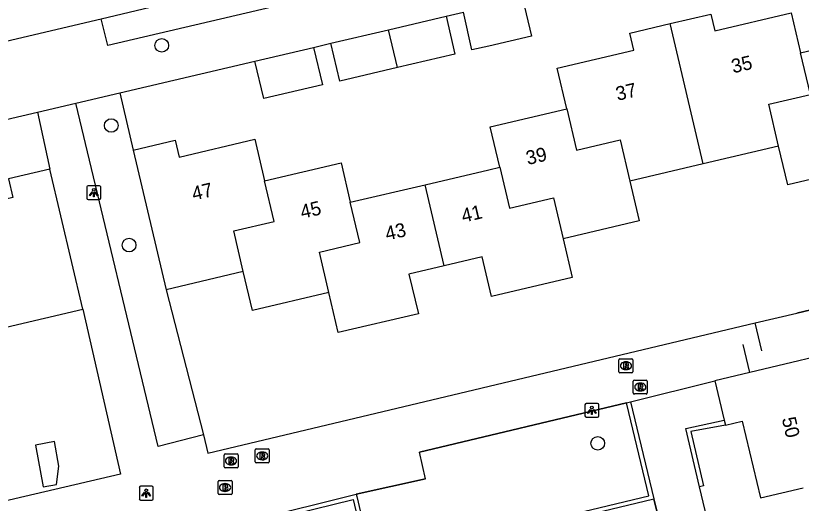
# Model space of a CAD drawing. Extents: x 158038 to 159242, y 380133 to 381214.
# Drawn here: x 158966.1 to 159022.4, y 380563.6 to 380598.6 of the extents above; entities that cross this region are included whole.
import ezdxf

# ---------------------------------------------------------------- set-up
doc = ezdxf.new("R2010")
doc.units = 0
for name, color, linetype in [('IMGEO_Boom', 7, 'Continuous'), ('IMGEO_Brandkraan', 7, 'Continuous'), ('IMGEO_Groenvoorziening', 7, 'Continuous'), ('IMGEO_Hek', 7, 'Continuous'), ('IMGEO_Lichtpunt', 7, 'Continuous'), ('IMGEO_Muur', 7, 'Continuous'), ('IMGEO_Pand', 7, 'Continuous'), ('IMGEO_Pand_nummerreeks', 7, 'Continuous'), ('IMGEO_Rijbaan_lokaal_gesloten', 7, 'Continuous'), ('IMGEO_Rioolput', 7, 'Continuous'), ('IMGEO_Voetpad_open', 7, 'Continuous')]:
    doc.layers.add(name, color=color, linetype=linetype)

msp = doc.modelspace()

# ---------------------------------------------------------------- linework, layer by layer
at = {"layer": 'IMGEO_Boom'}
for centre in [(158976.569, 380596.489), (158972.951, 380590.742), (158974.234, 380582.162), (159007.808, 380567.951)]:
    msp.add_circle(centre, 0.489, dxfattribs=at)
at = {"layer": 'IMGEO_Brandkraan'}
for p, q in [((158980.605, 380564.354), (158980.605, 380565.206)), ((158980.68, 380565.28), (158981.532, 380565.28)), ((158981.606, 380565.206), (158981.606, 380564.354)), ((158981.093, 380565.06), (158981.118, 380565.06)), ((158981.532, 380564.28), (158980.68, 380564.28)), ((158981.116, 380564.5), (158981.091, 380564.5))]:
    msp.add_line(p, q, dxfattribs=at)
for points in [[(158980.605, 380564.354), (158980.605, 380565.206)], [(158980.68, 380565.28), (158981.532, 380565.28)], [(158981.606, 380565.206), (158981.606, 380564.354)], [(158980.953, 380564.98), (158980.953, 380564.58), (158981.166, 380564.58)], [(158981.184, 380564.98), (158980.953, 380564.98)], [(158981.132, 380564.899), (158981.078, 380564.899), (158981.078, 380564.823)], [(158981.078, 380564.823), (158981.131, 380564.823)], [(158981.14, 380564.747), (158981.078, 380564.747), (158981.078, 380564.666)], [(158981.078, 380564.666), (158981.14, 380564.666)], [(158981.532, 380564.28), (158980.68, 380564.28)]]:
    msp.add_lwpolyline(points, dxfattribs=at)
for centre, radius, start, end in [((158980.682, 380565.204), 0.0765, 91.552, 178.448), ((158980.682, 380565.204), 0.0765, 91.552, 178.448), ((158981.53, 380565.204), 0.0765, 1.552, 88.448), ((158981.53, 380565.204), 0.0765, 1.552, 88.448), ((158981.133, 380564.861), 0.0379, 267.8285, 90.9355), ((158981.141, 380564.706), 0.0404, 269.8759, 90.5077), ((158981.188, 380564.835), 0.145, 59.4692, 91.5367), ((158981.213, 380564.882), 0.0922, 285.5137, 58.1501), ((158981.218, 380564.69), 0.105, 301.3115, 78.989), ((158980.682, 380564.356), 0.0765, 181.552, 268.448), ((158980.682, 380564.356), 0.0765, 181.552, 268.448), ((158981.172, 380564.831), 0.251, 268.6676, 293.5347), ((158981.53, 380564.356), 0.0765, 271.552, 358.448), ((158981.53, 380564.356), 0.0765, 271.552, 358.448)]:
    msp.add_arc(centre, radius, start, end, dxfattribs=at)
for centre, major_axis, ratio, start_param, end_param in [((158981.092, 380564.78), (-0.387, 0.002), 0.722429, 4.712389, 7.853982), ((158981.117, 380564.78), (-0.39, 0.002), 0.717154, 1.570796, 4.712389)]:
    msp.add_ellipse(centre, major_axis=major_axis, ratio=ratio, start_param=start_param, end_param=end_param, dxfattribs=at)
at = {"layer": 'IMGEO_Groenvoorziening'}
for points in [[(158973.574, 380593.09), (158974.529, 380588.981)], [(158976.886, 380578.968), (158979.549, 380568.549)]]:
    msp.add_lwpolyline(points, dxfattribs=at)
at = {"layer": 'IMGEO_Hek'}
for points in [[(159053.876, 380597.146), (159056.645, 380585.524), (159022.058, 380577.294)], [(159019.569, 380574.573), (159019.09, 380576.588)], [(159018.689, 380573.029), (159018.226, 380575.032)], [(159009.864, 380570.865), (158995.026, 380567.309)], [(158995.463, 380565.41), (158995.026, 380567.309)], [(158995.463, 380565.41), (158990.499, 380564.295)], [(159013.65, 380556.494), (159011.819, 380563.962)]]:
    msp.add_lwpolyline(points, dxfattribs=at)
at = {"layer": 'IMGEO_Lichtpunt'}
for p, q in [((158971.2, 380586.332), (158971.2, 380585.525)), ((158971.2, 380586.332), (158971.2, 380585.525)), ((158972.102, 380586.427), (158971.294, 380586.427)), ((158972.102, 380586.427), (158971.294, 380586.427)), ((158972.196, 380585.525), (158972.196, 380586.332)), ((158972.196, 380585.525), (158972.196, 380586.332)), ((158971.294, 380585.431), (158972.102, 380585.431)), ((158971.294, 380585.431), (158972.102, 380585.431)), ((159007.789, 380570.814), (159006.981, 380570.814)), ((159007.789, 380570.814), (159006.981, 380570.814)), ((159006.887, 380570.719), (159006.887, 380569.912)), ((159006.887, 380570.719), (159006.887, 380569.912)), ((159007.883, 380569.912), (159007.883, 380570.719)), ((159007.883, 380569.912), (159007.883, 380570.719)), ((159006.981, 380569.818), (159007.789, 380569.818)), ((159006.981, 380569.818), (159007.789, 380569.818)), ((158974.964, 380564.781), (158974.964, 380563.974)), ((158974.964, 380564.781), (158974.964, 380563.974)), ((158975.866, 380564.876), (158975.058, 380564.876)), ((158975.866, 380564.876), (158975.058, 380564.876)), ((158975.96, 380563.974), (158975.96, 380564.781)), ((158975.96, 380563.974), (158975.96, 380564.781)), ((158975.058, 380563.88), (158975.866, 380563.88)), ((158975.058, 380563.88), (158975.866, 380563.88))]:
    msp.add_line(p, q, dxfattribs=at)
for points in [[(158971.574, 380585.996), (158971.613, 380585.968), (158971.425, 380585.706), (158971.387, 380585.733), (158971.574, 380585.996)], [(158971.676, 380585.948), (158971.723, 380585.948), (158971.723, 380585.626), (158971.676, 380585.626), (158971.676, 380585.948)], [(158971.786, 380585.968), (158971.824, 380585.995), (158972.011, 380585.733), (158971.972, 380585.705), (158971.786, 380585.968)], [(159007.261, 380570.383), (159007.3, 380570.355), (159007.112, 380570.093), (159007.074, 380570.12), (159007.261, 380570.383)], [(159007.363, 380570.335), (159007.41, 380570.335), (159007.41, 380570.013), (159007.363, 380570.013), (159007.363, 380570.335)], [(159007.473, 380570.355), (159007.511, 380570.382), (159007.698, 380570.12), (159007.659, 380570.092), (159007.473, 380570.355)], [(158975.338, 380564.445), (158975.377, 380564.417), (158975.189, 380564.155), (158975.151, 380564.182), (158975.338, 380564.445)], [(158975.44, 380564.397), (158975.487, 380564.397), (158975.487, 380564.075), (158975.44, 380564.075), (158975.44, 380564.397)], [(158975.55, 380564.417), (158975.588, 380564.444), (158975.775, 380564.182), (158975.736, 380564.154), (158975.55, 380564.417)]]:
    msp.add_lwpolyline(points, dxfattribs=at)
for centre in [(158971.699, 380586.13), (159007.386, 380570.517), (158975.463, 380564.579)]:
    msp.add_circle(centre, 0.0994, dxfattribs=at)
for centre, start, end in [((158971.294, 380586.332), 90, 180), ((158971.294, 380586.332), 90, 180), ((158972.102, 380586.332), 0, 90), ((158972.102, 380586.332), 0, 90), ((158971.294, 380585.525), 180, 270), ((158971.294, 380585.525), 180, 270), ((158972.102, 380585.525), 270, 0), ((158972.102, 380585.525), 270, 360), ((159006.981, 380570.719), 90, 180), ((159006.981, 380570.719), 90, 180), ((159007.789, 380570.719), 0, 90), ((159007.789, 380570.719), 0, 90), ((159006.981, 380569.912), 180, 270), ((159006.981, 380569.912), 180, 270), ((159007.789, 380569.912), 270, 0), ((159007.789, 380569.912), 270, 360), ((158975.058, 380564.781), 90, 180), ((158975.058, 380564.781), 90, 180), ((158975.866, 380564.781), 0, 90), ((158975.866, 380564.781), 0, 90), ((158975.058, 380563.974), 180, 270), ((158975.058, 380563.974), 180, 270), ((158975.866, 380563.974), 270, 0), ((158975.866, 380563.974), 270, 360)]:
    msp.add_arc(centre, 0.0946, start, end, dxfattribs=at)
at = {"layer": 'IMGEO_Muur'}
for points in [[(158990.499, 380564.295), (158990.547, 380564.134), (158991.65, 380559.436), (159011.457, 380564.184), (159009.88, 380570.748), (159009.864, 380570.865)], [(159009.864, 380570.865), (159010.157, 380570.931)], [(159010.157, 380570.931), (159011.819, 380563.962)], [(159015.096, 380564.842), (159014.104, 380569.024), (159016.86, 380569.62)], [(159016.946, 380569.252), (159014.461, 380568.794), (159015.382, 380564.909), (159015.096, 380564.842)], [(158983.127, 380562.472), (158990.499, 380564.295)], [(158983.2, 380562.181), (158990.277, 380563.931), (158991.427, 380559.074)], [(158991.427, 380559.074), (159011.819, 380563.962)]]:
    msp.add_lwpolyline(points, dxfattribs=at)
at = {"layer": 'IMGEO_Pand'}
for points in [[(159002.421, 380599.87), (159003.063, 380597.158), (159000, 380596.441), (158998.794, 380596.159), (158998.195, 380598.879)], [(158992.818, 380597.61), (158996.933, 380598.578)], [(158996.933, 380598.578), (158997.572, 380595.86), (158993.457, 380594.892)], [(159012.994, 380598.052), (159015.901, 380598.736), (159016.183, 380597.537), (159021.662, 380598.826), (159022.337, 380595.959)], [(159005.582, 380591.929), (159004.893, 380594.857), (159010.379, 380596.148), (159010.091, 380597.369), (159012.994, 380598.052)], [(159015.36, 380587.994), (159012.994, 380598.052)], [(158988.693, 380596.64), (158992.818, 380597.61)], [(158993.457, 380594.892), (158992.818, 380597.61)], [(159022.337, 380595.959), (159027.797, 380597.244), (159028.477, 380594.357)], [(158983.249, 380595.352), (158987.446, 380596.339)], [(158987.446, 380596.339), (158988.076, 380593.662), (158983.878, 380592.675), (158983.249, 380595.352)], [(158993.457, 380594.892), (158989.332, 380593.922), (158988.693, 380596.64)], [(159020.76, 380589.264), (159020.055, 380592.26), (159023.042, 380592.963), (159022.337, 380595.959)], [(159000.785, 380587.749), (159000.108, 380590.641), (159005.582, 380591.929)], [(159005.582, 380591.929), (159006.277, 380588.975), (159009.409, 380589.711), (159010.104, 380586.757)], [(158974.529, 380588.981), (158977.53, 380589.687), (158977.816, 380588.475), (158983.242, 380589.752), (158983.941, 380586.782)], [(158974.529, 380588.981), (158976.886, 380578.968)], [(159020.76, 380589.264), (159015.36, 380587.994)], [(159026.885, 380587.776), (159021.413, 380586.489), (159020.76, 380589.264)], [(158983.941, 380586.782), (158989.411, 380588.069), (158990.078, 380585.233)], [(158995.432, 380586.493), (159000, 380587.568), (159000.785, 380587.749)], [(159000.785, 380587.749), (159001.472, 380584.815), (159004.63, 380585.557), (159005.321, 380582.622)], [(159015.36, 380587.994), (159010.104, 380586.757)], [(158968.543, 380587.612), (158965.586, 380586.912), (158965.902, 380585.578), (158960.384, 380584.272), (158961.051, 380581.455)], [(158970.916, 380577.581), (158968.543, 380587.612)], [(158982.409, 380580.268), (158981.723, 380583.183), (158984.627, 380583.867), (158983.941, 380586.782)], [(159010.104, 380586.757), (159010.775, 380583.905), (159005.321, 380582.622)], [(158990.078, 380585.233), (158995.432, 380586.493)], [(158996.797, 380580.685), (158995.432, 380586.493)], [(158988.539, 380578.772), (158987.859, 380581.662), (158990.758, 380582.343), (158990.078, 380585.233)], [(159005.321, 380582.622), (159005.973, 380579.852), (159000.181, 380578.49), (159000, 380579.301), (158999.524, 380581.327), (158996.797, 380580.685)], [(158996.797, 380580.685), (158994.28, 380580.093), (158994.951, 380577.242), (158989.216, 380575.893), (158988.539, 380578.772)], [(158982.409, 380580.268), (158976.886, 380578.968)], [(158988.539, 380578.772), (158983.064, 380577.484), (158982.409, 380580.268)], [(158965.416, 380576.279), (158970.916, 380577.581)], [(159026.354, 380574.719), (159026.324, 380574.845), (159018.689, 380573.029), (159016.2, 380572.436)], [(159016.2, 380572.436), (159016.86, 380569.62)], [(159016.86, 380569.62), (159016.946, 380569.252)], [(159016.946, 380569.252), (159018.161, 380569.541), (159019.47, 380564.04), (159022.511, 380564.758)], [(158967.515, 380567.83), (158968.075, 380564.819), (158969.023, 380564.995), (158969.208, 380566.317), (158968.88, 380568.083), (158967.515, 380567.83)]]:
    msp.add_lwpolyline(points, dxfattribs=at)
at = {"layer": 'IMGEO_Rijbaan_lokaal_gesloten'}
for points in [[(158972.222, 380598.401), (158999.117, 380604.815)], [(158958.59, 380595.188), (158972.222, 380598.401)]]:
    msp.add_lwpolyline(points, dxfattribs=at)
at = {"layer": 'IMGEO_Rioolput'}
for p, q in [((159009.322, 380573.089), (159009.322, 380573.941)), ((159009.397, 380574.015), (159010.249, 380574.015)), ((159009.81, 380573.795), (159009.835, 380573.795)), ((159010.323, 380573.941), (159010.323, 380573.089)), ((159009.833, 380573.235), (159009.808, 380573.235)), ((159010.249, 380573.015), (159009.397, 380573.015)), ((159010.35, 380571.562), (159010.35, 380572.414)), ((159010.425, 380572.488), (159011.277, 380572.488)), ((159010.838, 380572.268), (159010.863, 380572.268)), ((159011.351, 380572.414), (159011.351, 380571.562)), ((159011.277, 380571.488), (159010.425, 380571.488)), ((159010.861, 380571.708), (159010.836, 380571.708)), ((158983.267, 380566.623), (158983.267, 380567.475)), ((158983.342, 380567.549), (158984.194, 380567.549)), ((158984.268, 380567.475), (158984.268, 380566.623)), ((158981.034, 380566.26), (158981.034, 380567.112)), ((158981.109, 380567.186), (158981.961, 380567.186)), ((158981.522, 380566.966), (158981.547, 380566.966)), ((158982.035, 380567.112), (158982.035, 380566.26)), ((158983.755, 380567.329), (158983.78, 380567.329)), ((158981.545, 380566.406), (158981.52, 380566.406)), ((158984.194, 380566.549), (158983.342, 380566.549)), ((158983.778, 380566.769), (158983.753, 380566.769)), ((158981.961, 380566.186), (158981.109, 380566.186))]:
    msp.add_line(p, q, dxfattribs=at)
for points in [[(159009.322, 380573.089), (159009.322, 380573.941)], [(159009.397, 380574.015), (159010.249, 380574.015)], [(159009.911, 380573.713), (159009.659, 380573.715), (159009.659, 380573.315)], [(159009.837, 380573.634), (159009.783, 380573.634), (159009.783, 380573.553)], [(159010.323, 380573.941), (159010.323, 380573.089)], [(159009.659, 380573.315), (159009.783, 380573.315), (159009.783, 380573.477), (159009.794, 380573.477)], [(159009.783, 380573.553), (159009.835, 380573.553)], [(159009.841, 380573.448), (159009.912, 380573.315), (159010.052, 380573.315), (159009.987, 380573.441)], [(159010.249, 380573.015), (159009.397, 380573.015)], [(159010.35, 380571.562), (159010.35, 380572.414)], [(159010.425, 380572.488), (159011.277, 380572.488)], [(159010.939, 380572.186), (159010.687, 380572.188), (159010.687, 380571.788)], [(159010.687, 380571.788), (159010.811, 380571.788), (159010.811, 380571.95), (159010.822, 380571.95)], [(159010.865, 380572.107), (159010.811, 380572.107), (159010.811, 380572.026)], [(159010.811, 380572.026), (159010.863, 380572.026)], [(159011.351, 380572.414), (159011.351, 380571.562)], [(159011.277, 380571.488), (159010.425, 380571.488)], [(159010.869, 380571.921), (159010.94, 380571.788), (159011.08, 380571.788), (159011.015, 380571.914)], [(158983.267, 380566.623), (158983.267, 380567.475)], [(158983.342, 380567.549), (158984.194, 380567.549)], [(158984.268, 380567.475), (158984.268, 380566.623)], [(158981.034, 380566.26), (158981.034, 380567.112)], [(158981.109, 380567.186), (158981.961, 380567.186)], [(158981.623, 380566.884), (158981.371, 380566.886), (158981.371, 380566.486)], [(158982.035, 380567.112), (158982.035, 380566.26)], [(158983.856, 380567.247), (158983.604, 380567.249), (158983.604, 380566.849)], [(158983.604, 380566.849), (158983.728, 380566.849), (158983.728, 380567.011), (158983.739, 380567.011)], [(158983.782, 380567.168), (158983.728, 380567.168), (158983.728, 380567.087)], [(158983.728, 380567.087), (158983.78, 380567.087)], [(158983.786, 380566.982), (158983.857, 380566.849), (158983.997, 380566.849), (158983.932, 380566.975)], [(158981.371, 380566.486), (158981.495, 380566.486), (158981.495, 380566.648), (158981.506, 380566.648)], [(158981.549, 380566.805), (158981.495, 380566.805), (158981.495, 380566.724)], [(158981.495, 380566.724), (158981.547, 380566.724)], [(158981.553, 380566.619), (158981.624, 380566.486), (158981.764, 380566.486), (158981.699, 380566.612)], [(158984.194, 380566.549), (158983.342, 380566.549)], [(158981.961, 380566.186), (158981.109, 380566.186)]]:
    msp.add_lwpolyline(points, dxfattribs=at)
for centre, radius, start, end in [((159009.399, 380573.939), 0.0765, 91.552, 178.448), ((159009.399, 380573.939), 0.0765, 91.552, 178.448), ((159009.843, 380573.538), 0.0964, 77.0061, 93.1865), ((159009.857, 380573.595), 0.0378, 276.6634, 79.6772), ((159009.91, 380573.603), 0.109, 350.3612, 89.416), ((159010.247, 380573.939), 0.0765, 1.552, 88.448), ((159010.247, 380573.939), 0.0765, 1.552, 88.448), ((159009.399, 380573.091), 0.0765, 181.552, 268.448), ((159009.399, 380573.091), 0.0765, 181.552, 268.448), ((159009.793, 380573.424), 0.0533, 26.0293, 88.6989), ((159009.819, 380573.742), 0.19, 274.7715, 282.9687), ((159009.908, 380573.603), 0.112, 277.5842, 350.9817), ((159009.892, 380573.388), 0.108, 29.5134, 73.7905), ((159010.247, 380573.091), 0.0765, 271.552, 358.448), ((159010.247, 380573.091), 0.0765, 271.552, 358.448), ((159010.427, 380572.412), 0.0765, 91.552, 178.448), ((159010.427, 380572.412), 0.0765, 91.552, 178.448), ((159010.821, 380571.897), 0.0533, 26.0293, 88.6989), ((159010.847, 380572.215), 0.19, 274.7715, 282.9687), ((159010.871, 380572.011), 0.0964, 77.0061, 93.1865), ((159010.885, 380572.068), 0.0378, 276.6634, 79.6772), ((159010.938, 380572.076), 0.109, 350.3612, 89.416), ((159010.936, 380572.076), 0.112, 277.5842, 350.9817), ((159010.92, 380571.861), 0.108, 29.5134, 73.7905), ((159011.275, 380572.412), 0.0765, 1.552, 88.448), ((159011.275, 380572.412), 0.0765, 1.552, 88.448), ((159010.427, 380571.564), 0.0765, 181.552, 268.448), ((159010.427, 380571.564), 0.0765, 181.552, 268.448), ((159011.275, 380571.564), 0.0765, 271.552, 358.448), ((159011.275, 380571.564), 0.0765, 271.552, 358.448), ((158983.344, 380567.473), 0.0765, 91.552, 178.448), ((158983.344, 380567.473), 0.0765, 91.552, 178.448), ((158984.192, 380567.473), 0.0765, 1.552, 88.448), ((158984.192, 380567.473), 0.0765, 1.552, 88.448), ((158981.111, 380567.11), 0.0765, 91.552, 178.448), ((158981.111, 380567.11), 0.0765, 91.552, 178.448), ((158981.622, 380566.774), 0.109, 350.3612, 89.416), ((158981.959, 380567.11), 0.0765, 1.552, 88.448), ((158981.959, 380567.11), 0.0765, 1.552, 88.448), ((158983.738, 380566.958), 0.0533, 26.0293, 88.6989), ((158983.764, 380567.276), 0.19, 274.7715, 282.9687), ((158983.788, 380567.072), 0.0964, 77.0061, 93.1865), ((158983.802, 380567.129), 0.0378, 276.6634, 79.6772), ((158983.855, 380567.137), 0.109, 350.3612, 89.416), ((158983.853, 380567.137), 0.112, 277.5842, 350.9817), ((158983.837, 380566.922), 0.108, 29.5134, 73.7905), ((158981.505, 380566.595), 0.0533, 26.0293, 88.6989), ((158981.531, 380566.913), 0.19, 274.7715, 282.9687), ((158981.555, 380566.709), 0.0964, 77.0061, 93.1865), ((158981.569, 380566.766), 0.0378, 276.6634, 79.6772), ((158981.62, 380566.774), 0.112, 277.5842, 350.9817), ((158981.604, 380566.559), 0.108, 29.5134, 73.7905), ((158983.344, 380566.625), 0.0765, 181.552, 268.448), ((158983.344, 380566.625), 0.0765, 181.552, 268.448), ((158984.192, 380566.625), 0.0765, 271.552, 358.448), ((158984.192, 380566.625), 0.0765, 271.552, 358.448), ((158981.111, 380566.262), 0.0765, 181.552, 268.448), ((158981.111, 380566.262), 0.0765, 181.552, 268.448), ((158981.959, 380566.262), 0.0765, 271.552, 358.448), ((158981.959, 380566.262), 0.0765, 271.552, 358.448)]:
    msp.add_arc(centre, radius, start, end, dxfattribs=at)
for centre, major_axis, ratio, start_param, end_param in [((159009.809, 380573.515), (-0.387, 0.002), 0.722429, 4.712389, 7.853982), ((159009.834, 380573.515), (-0.39, 0.002), 0.717154, 1.570796, 4.712389), ((159010.837, 380571.988), (-0.387, 0.002), 0.722429, 4.712389, 7.853982), ((159010.862, 380571.988), (-0.39, 0.002), 0.717154, 1.570796, 4.712389), ((158981.521, 380566.686), (-0.387, 0.002), 0.722429, 4.712389, 7.853982), ((158981.546, 380566.686), (-0.39, 0.002), 0.717154, 1.570796, 4.712389), ((158983.754, 380567.049), (-0.387, 0.002), 0.722429, 4.712389, 7.853982), ((158983.779, 380567.049), (-0.39, 0.002), 0.717154, 1.570796, 4.712389)]:
    msp.add_ellipse(centre, major_axis=major_axis, ratio=ratio, start_param=start_param, end_param=end_param, dxfattribs=at)
at = {"layer": 'IMGEO_Voetpad_open'}
for points in [[(158999.117, 380604.815), (158998.971, 380604.768), (158998.829, 380604.708), (158998.694, 380604.635), (158998.565, 380604.551), (158998.445, 380604.456), (158998.333, 380604.35), (158998.232, 380604.235), (158998.141, 380604.111), (158997.098, 380602.563), (158997.073, 380602.535), (158996.949, 380602.413), (158996.815, 380602.303), (158996.671, 380602.205), (158996.519, 380602.12), (158996.36, 380602.049), (158996.196, 380601.993), (158972.718, 380596.478), (158972.222, 380598.401)], [(158996.933, 380598.578), (158998.195, 380598.879)], [(158987.446, 380596.339), (158988.693, 380596.64)], [(158973.574, 380593.09), (158983.249, 380595.352)], [(158970.411, 380592.351), (158973.574, 380593.09)], [(158967.665, 380591.69), (158970.411, 380592.351)], [(158979.549, 380568.549), (158976.322, 380567.72), (158970.411, 380592.351)], [(158957.853, 380589.399), (158967.665, 380591.69)], [(158967.665, 380591.69), (158968.543, 380587.612)], [(158979.549, 380568.549), (158979.88, 380567.255), (159019.09, 380576.588), (159022.058, 380577.294), (159056.645, 380585.524)], [(158970.916, 380577.581), (158973.618, 380565.749), (158948.632, 380559.912), (158935.017, 380556.675)], [(159010.157, 380570.931), (159016.2, 380572.436)], [(158990.499, 380564.295), (158995.463, 380565.41), (158995.026, 380567.309), (159009.864, 380570.865)], [(159015.767, 380562.036), (159015.096, 380564.842)], [(159011.819, 380563.962), (159013.65, 380556.494)]]:
    msp.add_lwpolyline(points, dxfattribs=at)

# ---------------------------------------------------------------- texts
at = {"layer": 'IMGEO_Pand_nummerreeks'}
for s, rotation, p in [('35', 13.2388, (159017.504, 380594.478)), ('37', 13.2423, (159009.223, 380592.507)), ('39', 13.2405, (159002.791, 380587.903)), ('47', 13.2435, (158978.856, 380585.35)), ('45', 13.2399, (158986.622, 380584.044)), ('41', 13.2047, (158998.163, 380583.765)), ('43', 13.2429, (158992.701, 380582.481)), ('50', 283.2703, (159020.985, 380569.719))]:
    msp.add_text(s, height=1, rotation=rotation, dxfattribs=at).set_placement(p)

doc.saveas('drawing.dxf')
